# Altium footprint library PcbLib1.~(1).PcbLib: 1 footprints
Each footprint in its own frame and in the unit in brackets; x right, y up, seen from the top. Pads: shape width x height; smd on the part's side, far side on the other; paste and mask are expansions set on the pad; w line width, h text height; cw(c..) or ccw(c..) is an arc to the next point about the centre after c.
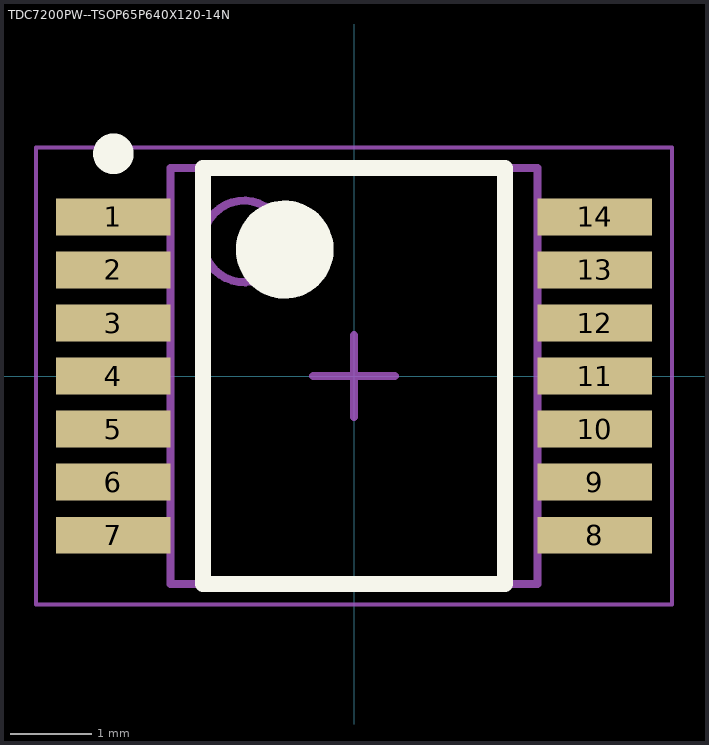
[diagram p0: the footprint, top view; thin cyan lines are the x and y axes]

## TDC7200PW--TSOP65P640X120-14N [mm] "TSOP, 14-Leads, Body 5.00x4.40mm, Pitch 0.65mm, IPC Medium Density"
height 1.2
pads (14):
  rect 1.4x0.45 smd: 1(-2.95,1.95) 2(-2.95,1.3) 3(-2.95,0.65) 4(-2.95,0) 5(-2.95,-0.65) 6(-2.95,-1.3) 7(-2.95,-1.95) 8(2.95,-1.95) 9(2.95,-1.3) 10(2.95,-0.65) 11(2.95,0) 12(2.95,0.65) 13(2.95,1.3) 14(2.95,1.95)
Top Overlay:
  circle w0.6: c-0.85,1.55 r0.3
  circle w0.25: c-2.95,2.725 r0.125
  lines w0.2: -1.85,-2.55 1.85,-2.55 1.85,2.55 -1.85,2.55 -1.85,-2.55
Mechanical 13:
  circle w0.1: c-1.35,1.65 r0.5
  lines w0.1: -2.25,-2.55 2.25,-2.55 2.25,2.55 -2.25,2.55 -2.25,-2.55
Mechanical 15:
  lines w0.05: -3.9,-2.8 3.9,-2.8 3.9,2.8 -3.9,2.8 -3.9,-2.8
  lines w0.1: -0.5,0 0.5,0 ; 0,-0.5 0,0.5
3D body: height 1.2, standoff 0.05, extent -2.25,-2.55 2.25,2.55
